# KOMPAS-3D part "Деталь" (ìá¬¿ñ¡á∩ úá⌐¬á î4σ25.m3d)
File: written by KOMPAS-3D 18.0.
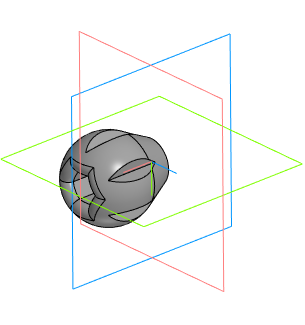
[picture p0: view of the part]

Document properties: Автор: Пользователь Windows; Полное имя файла: F:\Модели\Мех детали\Велосипед\Крепление фонаря\2\Накидная гайка М4х25.m3d

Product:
- Part/product: Деталь
    Масса: 0.0453094

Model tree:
1. Эскиз:1
2. Элемент вращения:1
     Угол 1 = 360
3. Эскиз:2  (with: Элемент вращения:1)
4. Элемент выдавливания:1
     Расстояние 1 = 30
5. Скругление:1  (with: Элемент вращения:1)
     Радиус = 2
6. Эскиз:3
7. Элемент выдавливания:2
     Расстояние 1 = 30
